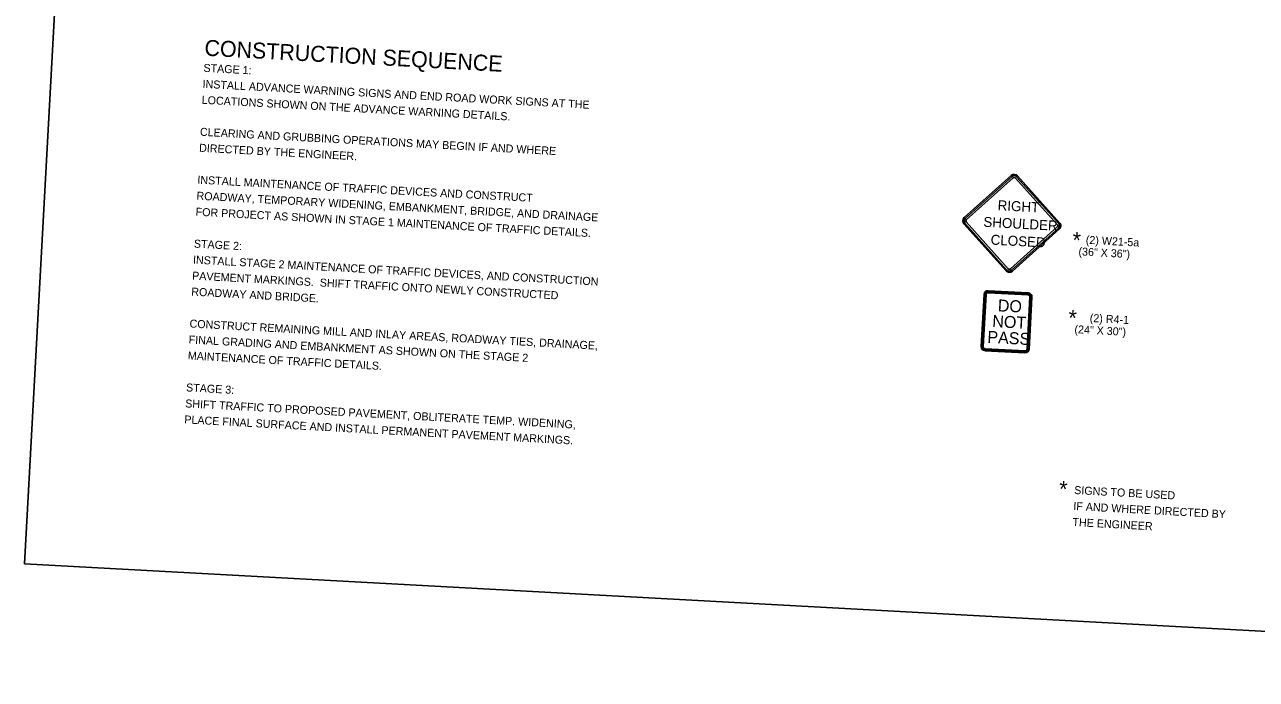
# Model space of a CAD drawing. Extents: x 879461 to 881100, y 1566470 to 1567598.
# Drawn here: x 879461 to 880385, y 1566470 to 1566961 of the extents above; entities that cross this region are included whole.
import ezdxf

# ---------------------------------------------------------------- set-up
doc = ezdxf.new("R2010")
doc.units = 0
for name, color, linetype in [('P_TC_Signs_Permanent', 7, 'Continuous'), ('P_TC_Signs_Temporary', 7, 'Continuous'), ('R_Annotation', 7, 'Continuous'), ('R_Border', 7, 'Continuous'), ('R_Draft', 7, 'Continuous'), ('R_No Plot', 7, 'Continuous')]:
    doc.layers.add(name, color=color, linetype=linetype)

msp = doc.modelspace()

# ---------------------------------------------------------------- linework, layer by layer
at = {"layer": 'P_TC_Signs_Permanent'}
for p, q in [((880213.77, 1566758.53), (880183.82, 1566760.16)), ((880213.82, 1566759.43), (880183.86, 1566761.06)), ((880213.85, 1566760.03), (880183.9, 1566761.66)), ((880180.74, 1566758.82), (880178.62, 1566719.88)), ((880181.34, 1566758.79), (880179.22, 1566719.85)), ((880182.24, 1566758.74), (880180.12, 1566719.8)), ((880213.07, 1566718.01), (880215.19, 1566756.95)), ((880213.97, 1566717.96), (880216.09, 1566756.9)), ((880214.57, 1566717.93), (880216.69, 1566756.87)), ((880181.45, 1566716.72), (880211.41, 1566715.09)), ((880181.49, 1566717.32), (880211.44, 1566715.69)), ((880181.53, 1566718.22), (880211.49, 1566716.59))]:
    msp.add_line(p, q, dxfattribs=at)
for centre, radius, start, end in [((880183.73, 1566758.66), 3, 86.8871, 176.8871), ((880183.73, 1566758.66), 2.4, 86.8871, 176.8871), ((880183.73, 1566758.66), 1.5, 86.8871, 176.8871), ((880213.69, 1566757.03), 3, 356.8871, 86.8871), ((880213.69, 1566757.03), 1.5, 356.8871, 86.8871), ((880213.69, 1566757.03), 2.4, 356.8871, 86.8871), ((880181.62, 1566719.72), 3, 176.8871, 266.8871), ((880181.62, 1566719.72), 2.4, 176.8871, 266.8871), ((880181.62, 1566719.72), 1.5, 176.8871, 266.8871), ((880211.57, 1566718.09), 3, 266.8871, 356.8871), ((880211.57, 1566718.09), 2.4, 266.8871, 356.8871), ((880211.57, 1566718.09), 1.5, 266.8871, 356.8871)]:
    msp.add_arc(centre, radius, start, end, dxfattribs=at)
at = {"layer": 'P_TC_Signs_Temporary'}
for p, q in [((880165.95, 1566816.51), (880201.13, 1566848.06)), ((880166.58, 1566815.82), (880201.75, 1566847.36)), ((880167.45, 1566814.84), (880202.63, 1566846.39)), ((880204.22, 1566846.3), (880235.76, 1566811.12)), ((880205.19, 1566847.18), (880236.74, 1566812)), ((880205.89, 1566847.8), (880237.44, 1566812.63)), ((880197.24, 1566776.57), (880165.69, 1566811.75)), ((880197.94, 1566777.2), (880166.39, 1566812.37)), ((880198.91, 1566778.07), (880167.37, 1566813.25)), ((880235.68, 1566809.53), (880200.5, 1566777.99)), ((880236.55, 1566808.56), (880201.38, 1566777.01)), ((880237.18, 1566807.86), (880202, 1566776.31))]:
    msp.add_line(p, q, dxfattribs=at)
for centre, radius, start, end in [((880203.38, 1566845.55), 3.38, 41.8871, 131.8871), ((880203.38, 1566845.55), 2.44, 41.8871, 131.8871), ((880203.38, 1566845.55), 1.13, 41.8871, 131.8871), ((880168.2, 1566814), 3.38, 131.8871, 221.8871), ((880168.2, 1566814), 2.44, 131.8871, 221.8871), ((880168.2, 1566814), 1.12, 131.8871, 221.8871), ((880234.93, 1566810.37), 1.12, 311.8871, 41.8871), ((880234.93, 1566810.37), 2.44, 311.8871, 41.8871), ((880234.93, 1566810.37), 3.38, 311.8871, 41.8871), ((880199.75, 1566778.82), 3.38, 221.8871, 311.8871), ((880199.75, 1566778.82), 2.44, 221.8871, 311.8871), ((880199.75, 1566778.82), 1.13, 221.8871, 311.8871)]:
    msp.add_arc(centre, radius, start, end, dxfattribs=at)
at = {"layer": 'R_No Plot'}
msp.add_lwpolyline([(881099.91, 1567310.44), (881054.22, 1566470.26), (879461.22, 1566556.89), (879517.82, 1567597.67), (880700.13, 1567533.37), (880697.45, 1567484.05), (880874.78, 1567474.4), (880873.82, 1567456.58), (880891.99, 1567455.59), (880892.17, 1567458.84), (880969.72, 1567454.62)], dxfattribs=at)

# ---------------------------------------------------------------- texts
at = {"layer": 'P_TC_Signs_Permanent'}
for s, rotation, p in [('DO', 356.8871, (880190.9, 1566746.25)), ('NOT', 356.84674, (880186.77, 1566734.47)), ('PASS', 356.8871, (880183.07, 1566722.64))]:
    msp.add_text(s, height=9, rotation=rotation, dxfattribs=at).set_placement(p)
at = {"layer": 'P_TC_Signs_Temporary'}
for s, p in [('RIGHT', (880190.81, 1566822.09)), ('SHOULDER', (880180.1, 1566809.63)), ('CLOSED', (880185.57, 1566796.29))]:
    msp.add_text(s, height=7.5, rotation=356.8871, dxfattribs=at).set_placement(p)
at = {"layer": 'R_Annotation'}
for s, height, p in [('CONSTRUCTION SEQUENCE', 12, (879595.86, 1566937.95)), ('STAGE 1:', 6, (879595.2, 1566925.85)), ('INSTALL ADVANCE WARNING SIGNS AND END ROAD WORK SIGNS AT THE', 6, (879594.55, 1566913.86)), ('LOCATIONS SHOWN ON THE ADVANCE WARNING DETAILS.  ', 6, (879593.9, 1566901.88)), ('CLEARING AND GRUBBING OPERATIONS MAY BEGIN IF AND WHERE', 6, (879592.59, 1566877.92)), ('DIRECTED BY THE ENGINEER.', 6, (879591.94, 1566865.93)), ('INSTALL MAINTENANCE OF TRAFFIC DEVICES AND CONSTRUCT ', 6, (879590.64, 1566841.97)), ('ROADWAY, TEMPORARY WIDENING, EMBANKMENT, BRIDGE, AND DRAINAGE ', 6, (879589.99, 1566829.99)), ('FOR PROJECT AS SHOWN IN STAGE 1 MAINTENANCE OF TRAFFIC DETAILS. ', 6, (879589.34, 1566818)), ('STAGE 2:', 6, (879588.03, 1566794.04)), ('(2) W21-5a', 6, (880256.96, 1566796.93)), ('INSTALL STAGE 2 MAINTENANCE OF TRAFFIC DEVICES, AND CONSTRUCTION ', 6, (879587.38, 1566782.06)), ('(36" X 36")', 6, (880251.47, 1566788.21)), ('PAVEMENT MARKINGS.  SHIFT TRAFFIC ONTO NEWLY CONSTRUCTED ', 6, (879586.73, 1566770.08)), ('ROADWAY AND BRIDGE. ', 6, (879586.08, 1566758.09)), ('(2) R4-1', 6, (880259.93, 1566738.29)), ('CONSTRUCT REMAINING MILL AND INLAY AREAS, ROADWAY TIES, DRAINAGE, ', 6, (879584.77, 1566734.13)), ('(24" X 30")', 6, (880248.45, 1566729.9)), ('FINAL GRADING AND EMBANKMENT AS SHOWN ON THE STAGE 2 ', 6, (879584.12, 1566722.15)), ('MAINTENANCE OF TRAFFIC DETAILS.', 6, (879583.47, 1566710.16)), ('STAGE 3:', 6, (879582.17, 1566686.2)), ('SHIFT TRAFFIC TO PROPOSED PAVEMENT, OBLITERATE TEMP. WIDENING,', 6, (879581.52, 1566674.22)), ('PLACE FINAL SURFACE AND INSTALL PERMANENT PAVEMENT MARKINGS.', 6, (879580.86, 1566662.23))]:
    msp.add_text(s, height=height, rotation=356.8871, dxfattribs=at).set_placement(p)
at = {"layer": 'R_Border'}
for p in [(880246.78, 1566793.79), (880243.71, 1566735.48), (880236.73, 1566607.17)]:
    msp.add_text('*', height=12, rotation=356.8871, dxfattribs=at).set_placement(p)
at = {"layer": 'R_Draft'}
for s, p in [('SIGNS TO BE USED', (880248.25, 1566609.27)), ('IF AND WHERE DIRECTED BY', (880247.6, 1566597.29)), ('THE ENGINEER', (880246.94, 1566585.31))]:
    msp.add_text(s, height=6, rotation=356.8871, dxfattribs=at).set_placement(p)

doc.saveas('drawing.dxf')
